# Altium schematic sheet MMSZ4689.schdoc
size 127 x 101 mm
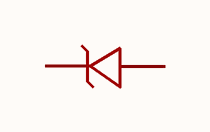
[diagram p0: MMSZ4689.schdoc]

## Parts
D?  mmsz4689_c21509  [SOD-123_L2.8-W1.8-LS3.7-RD]  (value not drawn)

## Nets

Not connected (* = marked no-connect by the designer): D? 1(K) 2(A)

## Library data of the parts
D? = mmsz4689_c21509: 二极管配置:1个独立式;稳压值(标称值):5.1V;稳压值(范围值):4.85V~5.36V;耗散功率(Pd):350mW;; Manufacturer: CJ(江苏长电/长晶); AddInBom: yes; ModelId: 7884390a25fb4c08947731ebfba7e3f8; ModelTransform: 144.8816,62.992,0,0,0,0,0,0,0; Diode Configuration: 1个独立式; Zener Voltage(Nom): 5.1V; Reverse Leakage Current (Ir): 10uA@3V; Pd - Power Dissipation: 350mW; Operating Junction Temperature Range: -65℃~+150℃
